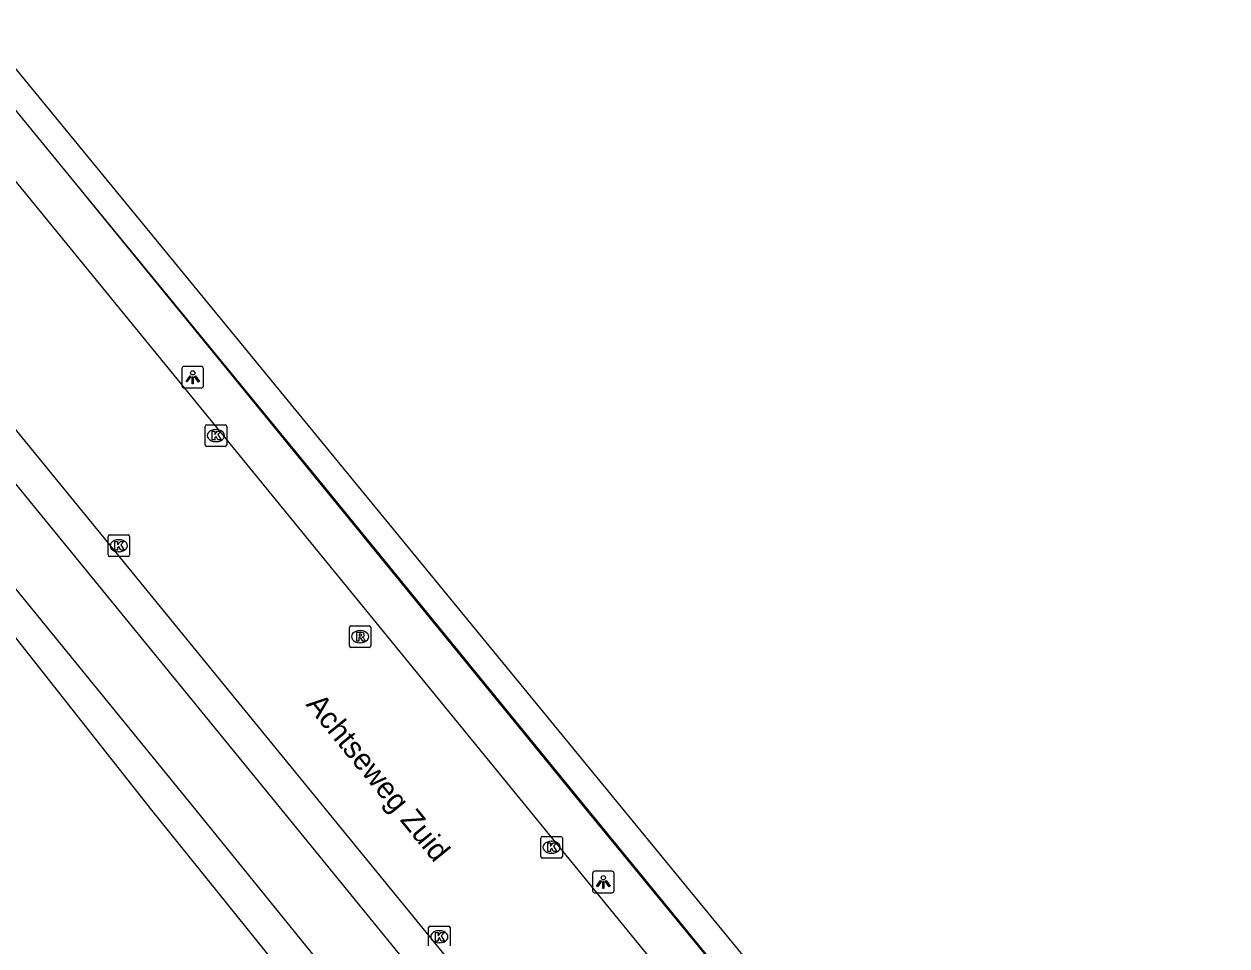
# Model space of a CAD drawing. Extents: x 157154 to 159278, y 385000 to 386650.
# Drawn here: x 158433.6 to 158489.4, y 386243.7 to 386286.5 of the extents above; entities that cross this region are included whole.
import ezdxf

# ---------------------------------------------------------------- set-up
doc = ezdxf.new("R2010")
doc.units = 0
for name, color, linetype in [('IMGEO_Berm_groen', 7, 'Continuous'), ('IMGEO_Fietspad_gesloten', 7, 'Continuous'), ('IMGEO_Hek', 7, 'Continuous'), ('IMGEO_Kolk', 7, 'Continuous'), ('IMGEO_Lichtpunt', 7, 'Continuous'), ('IMGEO_Loofbos', 7, 'Continuous'), ('IMGEO_Openbare_ruimte_label', 7, 'Continuous'), ('IMGEO_Rijbaan_lokaal_open', 7, 'Continuous'), ('IMGEO_Rioolput', 7, 'Continuous'), ('IMGEO_Spoorbaan_halfverhard', 7, 'Continuous')]:
    doc.layers.add(name, color=color, linetype=linetype)

msp = doc.modelspace()

# ---------------------------------------------------------------- linework, layer by layer
at = {"layer": 'IMGEO_Berm_groen'}
msp.add_lwpolyline([(158536.979, 386155.37), (158500.52, 386200.12), (158500, 386200.758), (158497.16, 386204.24), (158473.937, 386232.709), (158459.74, 386250), (158435.788, 386279.388), (158430.073, 386286.368)], dxfattribs=at)
at = {"layer": 'IMGEO_Fietspad_gesloten'}
for points in [[(158420.394, 386280.898), (158433.214, 386265.172), (158445.579, 386250), (158463.277, 386228.283), (158468.365, 386221.928), (158472.425, 386216.797)], [(158470.08, 386214.89), (158465.982, 386219.904), (158441.605, 386250), (158430.843, 386263.202), (158418.004, 386278.948)]]:
    msp.add_lwpolyline(points, dxfattribs=at)
at = {"layer": 'IMGEO_Hek'}
msp.add_lwpolyline([(158611.324, 386064.219), (158568.401, 386116.979), (158552.997, 386135.864), (158548.261, 386141.61), (158514.708, 386182.752), (158503.659, 386196.339), (158498.882, 386202.128), (158494.22, 386208.016), (158488.947, 386214.311), (158476.814, 386229.194), (158470.499, 386236.927), (158459.442, 386250.463), (158446.817, 386265.93), (158435.788, 386279.388), (158430.073, 386286.368)], dxfattribs=at)
at = {"layer": 'IMGEO_Kolk'}
for p, q in [((158442.025, 386266.974), (158442.025, 386267.826)), ((158442.1, 386267.9), (158442.952, 386267.9)), ((158442.513, 386267.68), (158442.538, 386267.68)), ((158443.026, 386267.826), (158443.026, 386266.974)), ((158442.952, 386266.9), (158442.1, 386266.9)), ((158442.536, 386267.12), (158442.511, 386267.12)), ((158437.518, 386261.858), (158437.518, 386262.71)), ((158437.593, 386262.784), (158438.445, 386262.784)), ((158438.006, 386262.564), (158438.031, 386262.564)), ((158438.519, 386262.71), (158438.519, 386261.858)), ((158438.029, 386262.004), (158438.004, 386262.004)), ((158438.445, 386261.784), (158437.593, 386261.784)), ((158457.597, 386247.858), (158457.597, 386248.71)), ((158457.672, 386248.784), (158458.524, 386248.784)), ((158458.085, 386248.564), (158458.11, 386248.564)), ((158458.598, 386248.71), (158458.598, 386247.858)), ((158458.108, 386248.004), (158458.083, 386248.004)), ((158458.524, 386247.784), (158457.672, 386247.784)), ((158452.39, 386243.702), (158452.39, 386244.554)), ((158452.465, 386244.628), (158453.317, 386244.628)), ((158453.391, 386244.554), (158453.391, 386243.702)), ((158452.878, 386244.408), (158452.903, 386244.408)), ((158452.901, 386243.848), (158452.876, 386243.848))]:
    msp.add_line(p, q, dxfattribs=at)
for points in [[(158442.025, 386266.974), (158442.025, 386267.826)], [(158442.1, 386267.9), (158442.952, 386267.9)], [(158442.346, 386267.6), (158442.469, 386267.6), (158442.469, 386267.449), (158442.599, 386267.6), (158442.763, 386267.6), (158442.617, 386267.449), (158442.77, 386267.2), (158442.618, 386267.2), (158442.533, 386267.364), (158442.469, 386267.297), (158442.469, 386267.2), (158442.346, 386267.2), (158442.346, 386267.6)], [(158443.026, 386267.826), (158443.026, 386266.974)], [(158442.952, 386266.9), (158442.1, 386266.9)], [(158437.518, 386261.858), (158437.518, 386262.71)], [(158437.593, 386262.784), (158438.445, 386262.784)], [(158437.839, 386262.484), (158437.962, 386262.484), (158437.962, 386262.333), (158438.092, 386262.484), (158438.256, 386262.484), (158438.11, 386262.333), (158438.263, 386262.084), (158438.111, 386262.084), (158438.026, 386262.248), (158437.962, 386262.181), (158437.962, 386262.084), (158437.839, 386262.084), (158437.839, 386262.484)], [(158438.519, 386262.71), (158438.519, 386261.858)], [(158438.445, 386261.784), (158437.593, 386261.784)], [(158457.597, 386247.858), (158457.597, 386248.71)], [(158457.672, 386248.784), (158458.524, 386248.784)], [(158457.918, 386248.484), (158458.041, 386248.484), (158458.041, 386248.333), (158458.171, 386248.484), (158458.335, 386248.484), (158458.189, 386248.333), (158458.342, 386248.084), (158458.19, 386248.084), (158458.105, 386248.248), (158458.041, 386248.181), (158458.041, 386248.084), (158457.918, 386248.084), (158457.918, 386248.484)], [(158458.598, 386248.71), (158458.598, 386247.858)], [(158458.524, 386247.784), (158457.672, 386247.784)], [(158452.39, 386243.702), (158452.39, 386244.554)], [(158452.465, 386244.628), (158453.317, 386244.628)], [(158453.391, 386244.554), (158453.391, 386243.702)], [(158452.711, 386244.328), (158452.834, 386244.328), (158452.834, 386244.177), (158452.964, 386244.328), (158453.128, 386244.328), (158452.982, 386244.177), (158453.135, 386243.928), (158452.983, 386243.928), (158452.898, 386244.092), (158452.834, 386244.025), (158452.834, 386243.928), (158452.711, 386243.928), (158452.711, 386244.328)]]:
    msp.add_lwpolyline(points, dxfattribs=at)
for centre, start, end in [((158442.102, 386267.824), 91.552, 178.448), ((158442.102, 386267.824), 91.552, 178.448), ((158442.95, 386267.824), 1.552, 88.448), ((158442.95, 386267.824), 1.552, 88.448), ((158442.102, 386266.976), 181.552, 268.448), ((158442.102, 386266.976), 181.552, 268.448), ((158442.95, 386266.976), 271.552, 358.448), ((158442.95, 386266.976), 271.552, 358.448), ((158437.595, 386262.708), 91.552, 178.448), ((158437.595, 386262.708), 91.552, 178.448), ((158438.443, 386262.708), 1.552, 88.448), ((158438.443, 386262.708), 1.552, 88.448), ((158437.595, 386261.86), 181.552, 268.448), ((158437.595, 386261.86), 181.552, 268.448), ((158438.443, 386261.86), 271.552, 358.448), ((158438.443, 386261.86), 271.552, 358.448), ((158457.674, 386248.708), 91.552, 178.448), ((158457.674, 386248.708), 91.552, 178.448), ((158458.522, 386248.708), 1.552, 88.448), ((158458.522, 386248.708), 1.552, 88.448), ((158457.674, 386247.86), 181.552, 268.448), ((158457.674, 386247.86), 181.552, 268.448), ((158458.522, 386247.86), 271.552, 358.448), ((158458.522, 386247.86), 271.552, 358.448), ((158452.467, 386244.552), 91.552, 178.448), ((158452.467, 386244.552), 91.552, 178.448), ((158453.315, 386244.552), 1.552, 88.448), ((158453.315, 386244.552), 1.552, 88.448)]:
    msp.add_arc(centre, 0.0765, start, end, dxfattribs=at)
for centre, major_axis, ratio, start_param, end_param in [((158442.512, 386267.4), (-0.387, 0.002), 0.722429, 4.712389, 7.853982), ((158442.537, 386267.4), (-0.39, 0.002), 0.717154, 1.570796, 4.712389), ((158438.005, 386262.284), (-0.387, 0.002), 0.722429, 4.712389, 7.853982), ((158438.03, 386262.284), (-0.39, 0.002), 0.717154, 1.570796, 4.712389), ((158458.084, 386248.284), (-0.387, 0.002), 0.722429, 4.712389, 7.853982), ((158458.109, 386248.284), (-0.39, 0.002), 0.717154, 1.570796, 4.712389), ((158452.877, 386244.128), (-0.387, 0.002), 0.722429, 4.712389, 7.853982), ((158452.902, 386244.128), (-0.39, 0.002), 0.717154, 1.570796, 4.712389)]:
    msp.add_ellipse(centre, major_axis=major_axis, ratio=ratio, start_param=start_param, end_param=end_param, dxfattribs=at)
at = {"layer": 'IMGEO_Lichtpunt'}
for p, q in [((158440.95, 386270.514), (158440.95, 386269.707)), ((158440.95, 386270.514), (158440.95, 386269.707)), ((158441.852, 386270.609), (158441.044, 386270.609)), ((158441.852, 386270.609), (158441.044, 386270.609)), ((158441.946, 386269.707), (158441.946, 386270.514)), ((158441.946, 386269.707), (158441.946, 386270.514)), ((158441.044, 386269.613), (158441.852, 386269.613)), ((158441.044, 386269.613), (158441.852, 386269.613)), ((158460.001, 386247.073), (158460.001, 386246.266)), ((158460.001, 386247.073), (158460.001, 386246.266)), ((158460.903, 386247.168), (158460.095, 386247.168)), ((158460.903, 386247.168), (158460.095, 386247.168)), ((158460.997, 386246.266), (158460.997, 386247.073)), ((158460.997, 386246.266), (158460.997, 386247.073)), ((158460.095, 386246.172), (158460.903, 386246.172)), ((158460.095, 386246.172), (158460.903, 386246.172))]:
    msp.add_line(p, q, dxfattribs=at)
for points in [[(158441.324, 386270.178), (158441.363, 386270.15), (158441.175, 386269.888), (158441.137, 386269.915), (158441.324, 386270.178)], [(158441.536, 386270.15), (158441.574, 386270.177), (158441.761, 386269.915), (158441.722, 386269.887), (158441.536, 386270.15)], [(158441.426, 386270.13), (158441.473, 386270.13), (158441.473, 386269.808), (158441.426, 386269.808), (158441.426, 386270.13)], [(158460.375, 386246.737), (158460.414, 386246.709), (158460.226, 386246.447), (158460.188, 386246.474), (158460.375, 386246.737)], [(158460.587, 386246.709), (158460.625, 386246.736), (158460.812, 386246.474), (158460.773, 386246.446), (158460.587, 386246.709)], [(158460.477, 386246.689), (158460.524, 386246.689), (158460.524, 386246.367), (158460.477, 386246.367), (158460.477, 386246.689)]]:
    msp.add_lwpolyline(points, dxfattribs=at)
for centre in [(158441.449, 386270.312), (158460.5, 386246.871)]:
    msp.add_circle(centre, 0.0994, dxfattribs=at)
for centre, start, end in [((158441.044, 386270.514), 90, 180), ((158441.044, 386270.514), 90, 180), ((158441.852, 386270.514), 0, 90), ((158441.852, 386270.514), 0, 90), ((158441.044, 386269.707), 180, 270), ((158441.044, 386269.707), 180, 270), ((158441.852, 386269.707), 270, 0), ((158441.852, 386269.707), 270, 360), ((158460.095, 386247.073), 90, 180), ((158460.095, 386247.073), 90, 180), ((158460.903, 386247.073), 0, 90), ((158460.903, 386247.073), 0, 90), ((158460.095, 386246.266), 180, 270), ((158460.095, 386246.266), 180, 270), ((158460.903, 386246.266), 270, 0), ((158460.903, 386246.266), 270, 360)]:
    msp.add_arc(centre, 0.0946, start, end, dxfattribs=at)
at = {"layer": 'IMGEO_Loofbos'}
msp.add_lwpolyline([(158448.729, 386238.609), (158439.557, 386250), (158417.422, 386278.073)], dxfattribs=at)
at = {"layer": 'IMGEO_Rijbaan_lokaal_open'}
for points in [[(158479.183, 386222.92), (158427.27, 386286.508)], [(158421.613, 386281.892), (158473.473, 386218.362)]]:
    msp.add_lwpolyline(points, dxfattribs=at)
at = {"layer": 'IMGEO_Rioolput'}
for p, q in [((158448.715, 386257.636), (158448.715, 386258.488)), ((158448.79, 386258.562), (158449.642, 386258.562)), ((158449.716, 386258.488), (158449.716, 386257.636)), ((158449.203, 386258.342), (158449.228, 386258.342)), ((158449.642, 386257.562), (158448.79, 386257.562)), ((158449.226, 386257.782), (158449.201, 386257.782))]:
    msp.add_line(p, q, dxfattribs=at)
for points in [[(158448.715, 386257.636), (158448.715, 386258.488)], [(158448.79, 386258.562), (158449.642, 386258.562)], [(158449.716, 386258.488), (158449.716, 386257.636)], [(158449.304, 386258.26), (158449.052, 386258.262), (158449.052, 386257.862)], [(158449.052, 386257.862), (158449.176, 386257.862), (158449.176, 386258.024), (158449.187, 386258.024)], [(158449.23, 386258.181), (158449.176, 386258.181), (158449.176, 386258.1)], [(158449.176, 386258.1), (158449.228, 386258.1)], [(158449.234, 386257.995), (158449.305, 386257.862), (158449.445, 386257.862), (158449.38, 386257.988)], [(158449.642, 386257.562), (158448.79, 386257.562)]]:
    msp.add_lwpolyline(points, dxfattribs=at)
for centre, radius, start, end in [((158448.792, 386258.486), 0.0765, 91.552, 178.448), ((158448.792, 386258.486), 0.0765, 91.552, 178.448), ((158449.64, 386258.486), 0.0765, 1.552, 88.448), ((158449.64, 386258.486), 0.0765, 1.552, 88.448), ((158449.186, 386257.971), 0.0533, 26.0293, 88.6989), ((158449.212, 386258.289), 0.19, 274.7715, 282.9687), ((158449.236, 386258.085), 0.0964, 77.0061, 93.1865), ((158449.25, 386258.142), 0.0378, 276.6634, 79.6772), ((158449.303, 386258.15), 0.109, 350.3612, 89.416), ((158449.301, 386258.15), 0.112, 277.5842, 350.9817), ((158449.285, 386257.935), 0.108, 29.5134, 73.7905), ((158448.792, 386257.638), 0.0765, 181.552, 268.448), ((158448.792, 386257.638), 0.0765, 181.552, 268.448), ((158449.64, 386257.638), 0.0765, 271.552, 358.448), ((158449.64, 386257.638), 0.0765, 271.552, 358.448)]:
    msp.add_arc(centre, radius, start, end, dxfattribs=at)
for centre, major_axis, ratio, start_param, end_param in [((158449.202, 386258.062), (-0.387, 0.002), 0.722429, 4.712389, 7.853982), ((158449.227, 386258.062), (-0.39, 0.002), 0.717154, 1.570796, 4.712389)]:
    msp.add_ellipse(centre, major_axis=major_axis, ratio=ratio, start_param=start_param, end_param=end_param, dxfattribs=at)
at = {"layer": 'IMGEO_Spoorbaan_halfverhard'}
msp.add_lwpolyline([(158432.682, 386285.09), (158523.052, 386174.84), (158539.004, 386155.645)], dxfattribs=at)

# ---------------------------------------------------------------- texts
at = {"layer": 'IMGEO_Openbare_ruimte_label'}
msp.add_text('Achtseweg Zuid', height=1, rotation=309.1967, dxfattribs=at).set_placement((158446.667, 386254.901))

doc.saveas('drawing.dxf')
